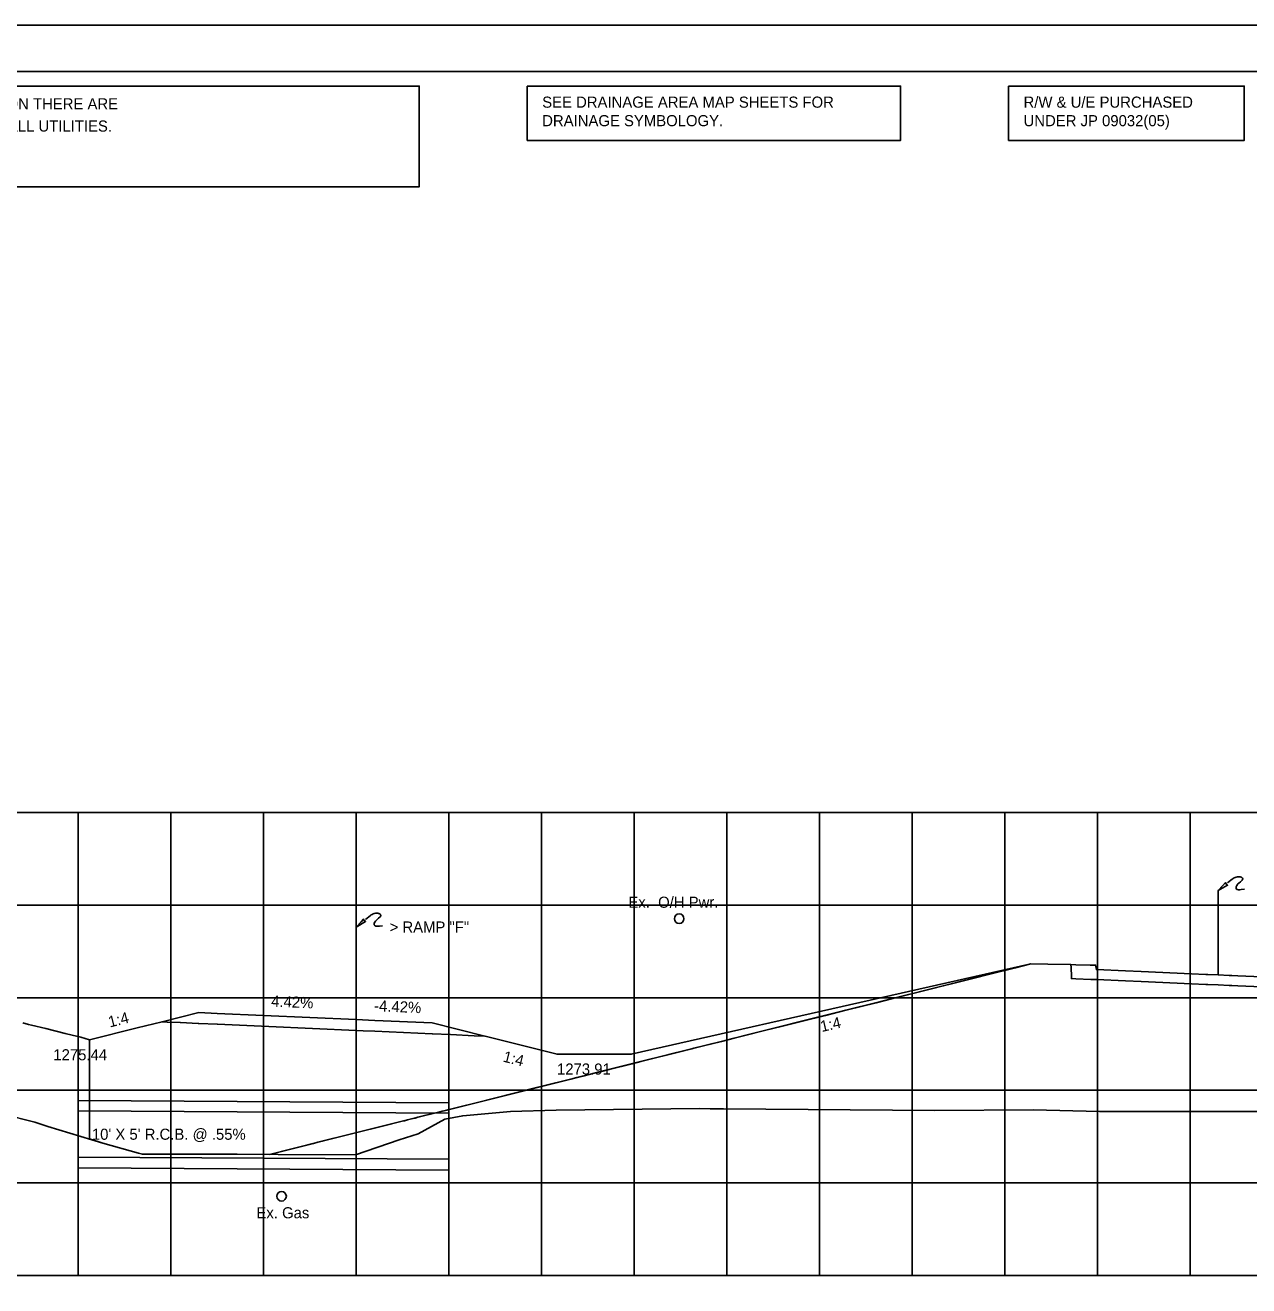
# Model space of a CAD drawing. Extents: x 2148105 to 2149976, y 144169 to 149705.
# Drawn here: x 2148377.6 to 2148509.6, y 147880.8 to 148016.9 of the extents above; entities that cross this region are included whole.
import ezdxf

# ---------------------------------------------------------------- set-up
doc = ezdxf.new("R2010")
doc.units = 0
for name, color, linetype in [('Bridge M-Header', 7, 'Continuous'), ('Default', 7, 'Continuous'), ('INR_Tracking', 7, 'Continuous'), ('Ph1-PR-Ramp SF3 Rev-Curb', 7, 'Continuous'), ('PH1a-2-RampC', 7, 'Continuous'), ('PH1a-PR-DividingStrip', 7, 'Continuous'), ('PH1a-PR-ServRd', 7, 'Continuous'), ('PH2-PR-Barrier', 7, 'Continuous'), ('PR-ApproachSlab', 7, 'Continuous'), ('PR-SHLDR-RMP-H', 7, 'Continuous'), ('PR_Align_Ramp_J', 7, 'Continuous'), ('PR_Storm_Channel', 7, 'Continuous'), ('PR_Storm_Conc_Box_PH1B', 7, 'Continuous'), ('PR_Storm_Conc_Pipe', 7, 'Continuous'), ('PR_Storm_Conc_Pipe_PH1B', 7, 'Continuous'), ('PR_Storm_Inlet_CICI_PH1B', 7, 'Continuous'), ('PR_Storm_Junction_Box_PH1A', 7, 'Continuous'), ('PR_Storm_MH', 7, 'Continuous'), ('PR_Storm_Standard_Median_Drain_PH1B', 7, 'Continuous'), ('PR_Storm_Txt', 7, 'Continuous'), ('TopCut', 7, 'Continuous')]:
    doc.layers.add(name, color=color, linetype=linetype)

# ---------------------------------------------------------------- blocks, each defined once
blk = doc.blocks.new('POINT_DISPLAY')
at = {"layer": 'Default'}
blk.add_line((0, 0), (0, 0), dxfattribs=at)

msp = doc.modelspace()

# ---------------------------------------------------------------- linework, layer by layer
at = {"layer": 'INR_Tracking'}
msp.add_lwpolyline([(2148384.52, 147907.35), (2148389.68, 147908.64), (2148392.36, 147909.31), (2148392.93, 147909.28), (2148394.33, 147909.22), (2148394.36, 147909.22), (2148396.26, 147909.13), (2148396.32, 147909.13), (2148398.32, 147909.04), (2148398.33, 147909.04), (2148403.88, 147908.8), (2148413.32, 147908.38), (2148413.34, 147908.38), (2148414.08, 147908.34), (2148415.32, 147908.29), (2148415.33, 147908.29), (2148421.52, 147908.02), (2148421.52, 147908.02), (2148423.51, 147907.93), (2148423.51, 147907.93), (2148426.06, 147907.81), (2148427.19, 147907.76), (2148427.2, 147907.76), (2148427.22, 147907.76), (2148435, 147905.81), (2148435.07, 147905.81), (2148443, 147905.81), (2148471.02, 147912.14), (2148486.12, 147915.55)], dxfattribs=at)
at = {"layer": 'Ph1-PR-Ramp SF3 Rev-Curb'}
for points in [[(2148383.32, 147900.8), (2148423.32, 147900.55)], [(2148383.32, 147899.71), (2148423.32, 147899.46)], [(2148383.32, 147894.71), (2148423.32, 147894.46)], [(2148383.32, 147893.55), (2148423.32, 147893.3)]]:
    msp.add_lwpolyline(points, dxfattribs=at)
at = {"layer": 'PH1a-PR-ServRd'}
msp.add_lwpolyline([(2148570.82, 147801.91), (2148255.82, 147801.91), (2148255.82, 148011.91), (2148570.82, 148011.91)], close=True, dxfattribs=at)
at = {"layer": 'PH2-PR-Barrier'}
msp.add_line((2148413.32, 147909.54), (2148413.32, 147919.54), dxfattribs=at)
for points in [[(2148413.32, 147919.54), (2148413.84, 147920.09), (2148414.1, 147920.4), (2148414.18, 147920.23), (2148414.32, 147920.12), (2148413.32, 147919.54)], [(2148414.33, 147920.36), (2148414.69, 147920.65), (2148414.85, 147920.78), (2148414.94, 147920.85), (2148415.04, 147920.91), (2148415.14, 147920.95), (2148415.26, 147920.99), (2148415.39, 147921.02), (2148415.49, 147921.03), (2148415.57, 147921.03), (2148415.65, 147921.02), (2148415.72, 147921.01), (2148415.78, 147920.99), (2148415.83, 147920.97), (2148415.87, 147920.95), (2148415.91, 147920.92), (2148415.95, 147920.87), (2148415.98, 147920.82), (2148415.97, 147920.76), (2148415.96, 147920.72), (2148415.91, 147920.65), (2148415.72, 147920.49), (2148415.53, 147920.32), (2148415.46, 147920.25), (2148415.39, 147920.17), (2148415.33, 147920.08), (2148415.29, 147920.02), (2148415.25, 147919.93), (2148415.25, 147919.85), (2148415.27, 147919.77), (2148415.31, 147919.7), (2148415.36, 147919.66), (2148415.42, 147919.64), (2148415.53, 147919.62), (2148415.66, 147919.63), (2148415.82, 147919.65), (2148416.15, 147919.68)]]:
    msp.add_lwpolyline(points, dxfattribs=at)
at = {"layer": 'PR-ApproachSlab'}
msp.add_lwpolyline([(2148403.96, 147894.99), (2148406.37, 147895.59), (2148409.65, 147896.41), (2148418.28, 147898.57), (2148418.53, 147898.63), (2148418.84, 147898.71), (2148419.3, 147898.83), (2148419.67, 147898.92), (2148419.98, 147899), (2148420.27, 147899.07), (2148420.54, 147899.14), (2148422.35, 147899.59), (2148422.61, 147899.65), (2148422.61, 147899.65), (2148422.79, 147899.7), (2148422.8, 147899.7), (2148422.95, 147899.74), (2148423.08, 147899.77), (2148423.2, 147899.8), (2148423.53, 147899.88), (2148435.89, 147902.98), (2148436.47, 147903.12), (2148437.13, 147903.29), (2148439.79, 147903.95), (2148440.61, 147904.16), (2148443.09, 147904.78), (2148444.05, 147905.02), (2148446.34, 147905.59), (2148447.44, 147905.87), (2148449.55, 147906.39), (2148449.77, 147906.45), (2148450.8, 147906.71), (2148452.73, 147907.19), (2148454.12, 147907.54), (2148455.66, 147907.92), (2148457.38, 147908.36), (2148459.31, 147908.84), (2148461.48, 147909.38), (2148463.95, 147910), (2148466.16, 147910.56), (2148467.6, 147910.91), (2148468.2, 147911.06), (2148471.33, 147911.85), (2148474.97, 147912.76), (2148479.23, 147913.83), (2148484.31, 147915.1), (2148484.47, 147915.14), (2148486.12, 147915.55), (2148487.96, 147915.52), (2148490.45, 147915.48), (2148490.98, 147915.47), (2148492.51, 147915.44), (2148492.52, 147915.44), (2148492.52, 147915.44), (2148492.66, 147915.44), (2148493.11, 147915.44), (2148493.17, 147915.1), (2148493.2, 147914.94), (2148493.2, 147914.94), (2148493.2, 147914.94), (2148496.35, 147914.81), (2148498.03, 147914.73), (2148503.48, 147914.49), (2148505, 147914.43), (2148505.24, 147914.42), (2148506.33, 147914.37), (2148506.34, 147914.37), (2148506.34, 147914.37), (2148506.35, 147914.37), (2148506.35, 147914.37), (2148507.54, 147914.32), (2148507.8, 147914.31), (2148508.45, 147914.28), (2148511.91, 147914.13)], dxfattribs=at)
at = {"layer": 'PR-SHLDR-RMP-H'}
msp.add_lwpolyline([(2148403.96, 147894.99), (2148408.71, 147896.18), (2148409.19, 147896.3), (2148416.58, 147898.15), (2148417.85, 147898.47), (2148424.35, 147900.09), (2148426.39, 147900.6), (2148432.06, 147902.02), (2148437.76, 147903.45), (2148439.67, 147903.93), (2148444.7, 147905.19), (2148447.22, 147905.82), (2148450.64, 147906.67), (2148453.14, 147907.3), (2148453.96, 147907.5), (2148454.7, 147907.69), (2148458.11, 147908.54), (2148462.1, 147909.54), (2148464.71, 147910.19), (2148469.42, 147911.37), (2148471.24, 147911.83), (2148476.68, 147913.19), (2148477.71, 147913.45), (2148483.86, 147914.99), (2148484.11, 147915.05), (2148486.12, 147915.55), (2148487.96, 147915.52), (2148490.45, 147915.48), (2148490.46, 147915.17), (2148490.46, 147915.14), (2148490.47, 147915.14), (2148490.47, 147915.14), (2148490.48, 147915.08), (2148490.5, 147914.31), (2148490.51, 147914), (2148490.51, 147913.98), (2148490.98, 147913.96), (2148492.59, 147913.89), (2148493.2, 147913.86), (2148493.2, 147913.86), (2148493.2, 147913.86), (2148496.35, 147913.72), (2148498.03, 147913.65), (2148503.48, 147913.41), (2148505, 147913.35), (2148505.24, 147913.33), (2148506.33, 147913.29), (2148506.34, 147913.29), (2148506.34, 147913.29), (2148506.35, 147913.29), (2148506.35, 147913.29), (2148507.54, 147913.23), (2148507.8, 147913.22), (2148508.45, 147913.19), (2148511.91, 147913.04)], dxfattribs=at)
at = {"layer": 'PR_Align_Ramp_J'}
msp.add_lwpolyline([(2148236.32, 148016.91), (2148576.32, 148016.91), (2148576.32, 147796.91), (2148236.32, 147796.91)], close=True, dxfattribs=at)
at = {"layer": 'PR_Storm_Channel'}
msp.add_lwpolyline([(2148392.36, 147909.3), (2148396.32, 147910.3), (2148398.32, 147910.21), (2148413.32, 147909.54), (2148415.32, 147909.46), (2148421.52, 147909.18), (2148427.2, 147907.76)], dxfattribs=at)
at = {"layer": 'PR_Storm_Conc_Box_PH1B'}
for p, q in [((2148263.32, 147931.91), (2148563.32, 147931.91)), ((2148383.32, 147881.91), (2148383.32, 147931.91)), ((2148393.32, 147881.91), (2148393.32, 147931.91)), ((2148403.32, 147881.91), (2148403.32, 147931.91)), ((2148413.32, 147881.91), (2148413.32, 147931.91)), ((2148423.32, 147881.91), (2148423.32, 147931.91)), ((2148433.32, 147881.91), (2148433.32, 147931.91)), ((2148443.32, 147881.91), (2148443.32, 147931.91)), ((2148453.32, 147881.91), (2148453.32, 147931.91)), ((2148463.32, 147881.91), (2148463.32, 147931.91)), ((2148473.32, 147881.91), (2148473.32, 147931.91)), ((2148483.32, 147881.91), (2148483.32, 147931.91)), ((2148493.32, 147881.91), (2148493.32, 147931.91)), ((2148503.32, 147881.91), (2148503.32, 147931.91)), ((2148263.32, 147921.91), (2148563.32, 147921.91)), ((2148263.32, 147911.91), (2148563.32, 147911.91)), ((2148263.32, 147901.91), (2148563.32, 147901.91)), ((2148263.32, 147891.91), (2148563.32, 147891.91)), ((2148263.32, 147881.91), (2148563.32, 147881.91))]:
    msp.add_line(p, q, dxfattribs=at)
at = {"layer": 'PR_Storm_Conc_Pipe'}
msp.add_lwpolyline([(2148377.34, 147909.18), (2148377.94, 147909.03), (2148378.26, 147908.95), (2148379.83, 147908.57), (2148381.92, 147908.05), (2148383.26, 147907.73), (2148383.31, 147907.71), (2148383.6, 147907.64), (2148384.52, 147907.35)], dxfattribs=at)
at = {"layer": 'PR_Storm_Conc_Pipe_PH1B'}
msp.add_lwpolyline([(2148255.82, 147801.91), (2148570.82, 147801.91), (2148570.82, 148011.91), (2148255.82, 148011.91)], close=True, dxfattribs=at)
msp.add_lwpolyline([(2148255.82, 147801.91), (2148570.82, 147801.91), (2148570.82, 148011.91), (2148255.82, 148011.91)], close=True, dxfattribs=at)
at = {"layer": 'PR_Storm_Inlet_CICI_PH1B'}
msp.add_lwpolyline([(2148375.21, 147899.32), (2148378.63, 147898.48), (2148380.05, 147898.02), (2148385.98, 147896.22), (2148389.83, 147895.12), (2148390.24, 147895.01), (2148393.45, 147895.02), (2148394.04, 147895.03), (2148404.89, 147894.99), (2148413.25, 147894.96), (2148417.94, 147896.57), (2148420, 147897.21), (2148422.89, 147898.81), (2148424.81, 147899.16), (2148429.96, 147899.64), (2148434.9, 147899.78), (2148450.36, 147899.94), (2148451.51, 147899.92), (2148452.94, 147899.91), (2148475.78, 147899.73), (2148486.36, 147899.79), (2148493.55, 147899.64), (2148516.2, 147899.62)], dxfattribs=at)
at = {"layer": 'PR_Storm_Junction_Box_PH1A'}
for centre in [(2148448.17, 147920.44), (2148405.26, 147890.47)]:
    msp.add_circle(centre, 0.516, dxfattribs=at)
at = {"layer": 'PR_Storm_MH'}
for points in [[(2148257.69, 148010.34), (2148420.12, 148010.34), (2148420.12, 147999.47), (2148257.69, 147999.47)], [(2148431.78, 148010.34), (2148472.07, 148010.34), (2148472.07, 148004.47), (2148431.78, 148004.47)], [(2148483.72, 148010.34), (2148509.15, 148010.34), (2148509.15, 148004.47), (2148483.72, 148004.47)]]:
    msp.add_lwpolyline(points, close=True, dxfattribs=at)
at = {"layer": 'PR_Storm_Standard_Median_Drain_PH1B'}
msp.add_line((2148263.32, 147881.91), (2148563.32, 147881.91), dxfattribs=at)
at = {"layer": 'PR_Storm_Txt'}
msp.add_line((2148506.34, 147914.37), (2148506.34, 147923.49), dxfattribs=at)
for points in [[(2148506.34, 147923.49), (2148506.86, 147924.04), (2148507.12, 147924.34), (2148507.2, 147924.18), (2148507.35, 147924.06), (2148506.34, 147923.49)], [(2148507.36, 147924.3), (2148507.71, 147924.59), (2148507.87, 147924.72), (2148507.97, 147924.79), (2148508.07, 147924.85), (2148508.16, 147924.89), (2148508.28, 147924.93), (2148508.42, 147924.96), (2148508.51, 147924.97), (2148508.59, 147924.97), (2148508.68, 147924.96), (2148508.75, 147924.95), (2148508.8, 147924.94), (2148508.85, 147924.92), (2148508.9, 147924.89), (2148508.93, 147924.86), (2148508.97, 147924.81), (2148509, 147924.76), (2148509, 147924.7), (2148508.98, 147924.66), (2148508.93, 147924.59), (2148508.74, 147924.43), (2148508.56, 147924.27), (2148508.48, 147924.19), (2148508.42, 147924.12), (2148508.35, 147924.02), (2148508.32, 147923.96), (2148508.28, 147923.87), (2148508.27, 147923.79), (2148508.29, 147923.71), (2148508.33, 147923.64), (2148508.38, 147923.61), (2148508.44, 147923.58), (2148508.55, 147923.57), (2148508.68, 147923.57), (2148508.84, 147923.59), (2148509.18, 147923.63)]]:
    msp.add_lwpolyline(points, dxfattribs=at)
at = {"layer": 'TopCut'}
msp.add_lwpolyline([(2148384.52, 147907.35), (2148384.52, 147896.67), (2148385.98, 147896.22), (2148389.83, 147895.12), (2148390.24, 147895.01), (2148393.45, 147895.02), (2148394.04, 147895.03), (2148397.98, 147895.01), (2148400.46, 147895), (2148403.96, 147894.99), (2148408.71, 147896.18), (2148409.19, 147896.3), (2148416.58, 147898.15), (2148417.85, 147898.47), (2148424.35, 147900.09), (2148426.39, 147900.6), (2148432.06, 147902.02), (2148437.76, 147903.45), (2148439.67, 147903.93), (2148444.29, 147905.11), (2148444.7, 147905.19), (2148447.22, 147905.82), (2148450.64, 147906.67), (2148453.14, 147907.3), (2148453.96, 147907.5), (2148454.7, 147907.69), (2148458.11, 147908.54), (2148462.1, 147909.54), (2148464.71, 147910.19), (2148469.42, 147911.37), (2148471.24, 147911.83), (2148476.68, 147913.19), (2148477.71, 147913.45), (2148483.86, 147914.99), (2148484.11, 147915.05), (2148486.11, 147915.55), (2148471.02, 147912.14), (2148443, 147905.81), (2148435.07, 147905.81), (2148435, 147905.81), (2148427.22, 147907.76), (2148427.2, 147907.76), (2148427.19, 147907.76), (2148426.06, 147907.81), (2148423.51, 147907.93), (2148423.51, 147907.93), (2148421.52, 147908.02), (2148421.52, 147908.02), (2148415.33, 147908.29), (2148415.32, 147908.29), (2148414.08, 147908.34), (2148413.34, 147908.38), (2148413.32, 147908.38), (2148403.88, 147908.8), (2148398.33, 147909.04), (2148398.32, 147909.04), (2148396.32, 147909.13), (2148396.26, 147909.13), (2148394.36, 147909.22), (2148394.33, 147909.22), (2148392.93, 147909.28), (2148392.36, 147909.31), (2148389.68, 147908.64)], close=True, dxfattribs=at)

# ---------------------------------------------------------------- block references
at = {"layer": 'PR_Storm_Conc_Pipe_PH1B', "xscale": 10, "yscale": 10}
for p in [(2148398.32, 147910.21), (2148398.32, 147910.21), (2148415.32, 147909.46), (2148415.32, 147909.46), (2148421.52, 147909.18), (2148421.52, 147909.18)]:
    msp.add_blockref('POINT_DISPLAY', p, dxfattribs=at)

# ---------------------------------------------------------------- texts
at = {"layer": 'Bridge M-Header'}
for s, p in [('4.42%', (2148404.12, 147910.95)), ('-4.42%', (2148415.23, 147910.46))]:
    msp.add_text(s, height=1.2, rotation=357.4668, dxfattribs=at).set_placement(p)
at = {"layer": 'PH1a-2-RampC'}
for s, p in [('1275.44', (2148380.63, 147905.15)), ('1273.91', (2148434.99, 147903.61)), ("10' X 5' R.C.B. @ .55%", (2148384.79, 147896.57))]:
    msp.add_text(s, height=1.2, dxfattribs=at).set_placement(p)
at = {"layer": 'PH1a-PR-DividingStrip'}
for rotation, p in [(14.0367, (2148386.72, 147908.69)), (12.7246, (2148463.55, 147908.2)), (345.9627, (2148429.08, 147905.02))]:
    msp.add_text('1:4', height=1.2, rotation=rotation, dxfattribs=at).set_placement(p)
at = {"layer": 'PH2-PR-Barrier'}
msp.add_text('> RAMP "F"', height=1.2, rotation=360, dxfattribs=at).set_placement((2148416.92, 147918.94))
at = {"layer": 'PR_Storm_Junction_Box_PH1A'}
for s, p in [('Ex.  O/H Pwr.', (2148442.69, 147921.62)), ('Ex. Gas', (2148402.55, 147888.09))]:
    msp.add_text(s, height=1.2, rotation=360, dxfattribs=at).set_placement(p)
at = {"layer": 'PR_Storm_MH'}
for s, p in [("(CAUTION) THE LOCATION OF ALL UTILITIES AS SHOWN ARE APPROXIMATE. DUE TO RELOCATION'S PLANNED OR PRESENTLY UNDER CONSTRUCTION THERE ARE ", (2148258.92, 148007.82)), ('SEE DRAINAGE AREA MAP SHEETS FOR', (2148433.39, 148008)), ('R/W & U/E PURCHASED', (2148485.34, 148008)), ('DRAINAGE SYMBOLOGY.', (2148433.39, 148006)), ('UNDER JP 09032(05)', (2148485.34, 148006)), ('SOME UTILITIES THAT WILL BE RELOCATED AND NOT SHOWN ON THESE PLANS. THE CONTRACTOR SHALL BE RESPONSIBLE FOR ANY DAMAGE TO ALL UTILITIES.', (2148258.92, 148005.42))]:
    msp.add_text(s, height=1.2, dxfattribs=at).set_placement(p)

doc.saveas('drawing.dxf')
